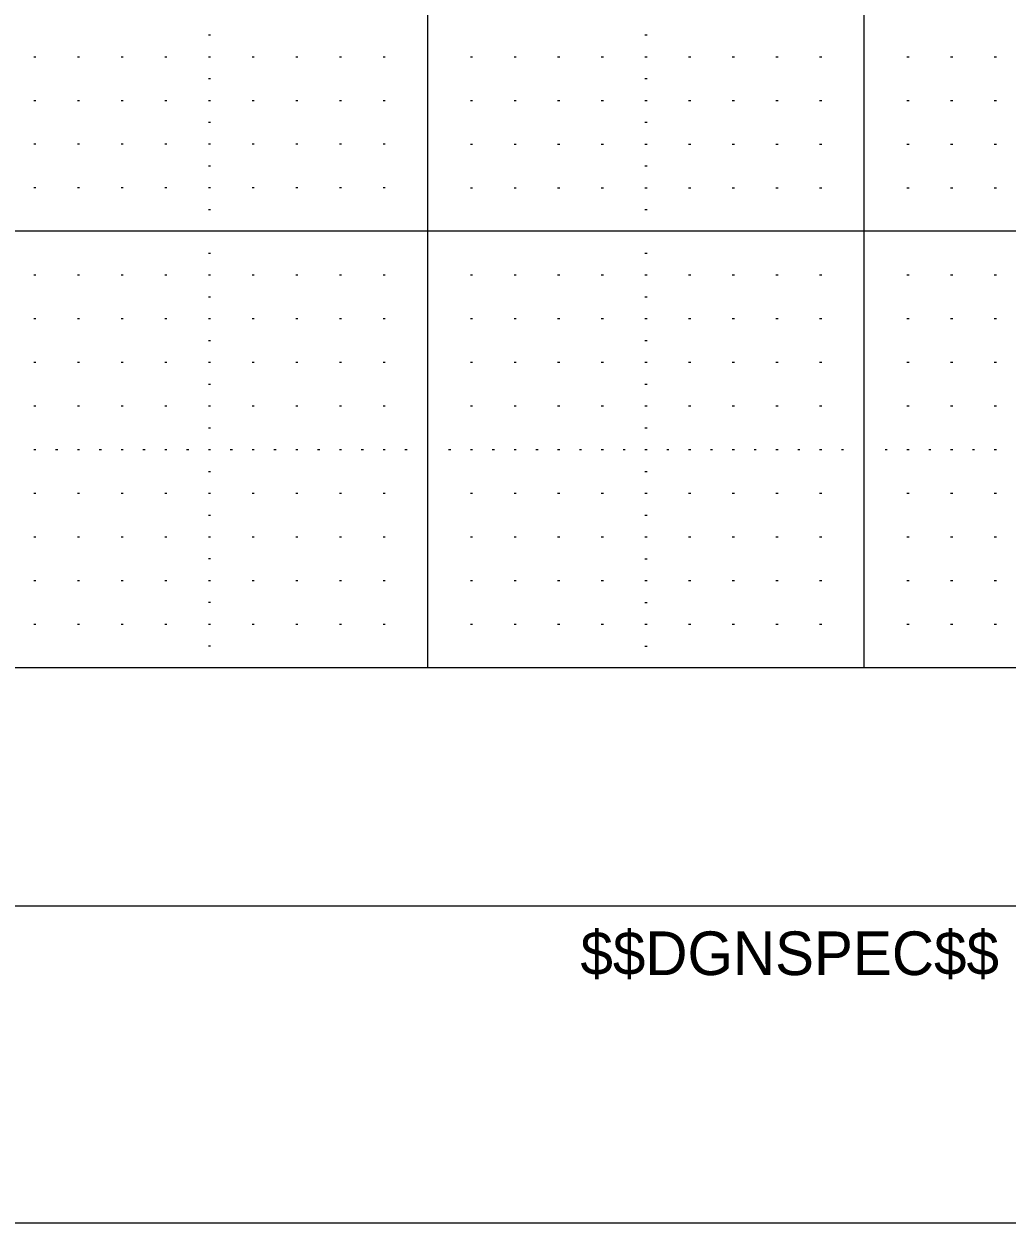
# Model space of a CAD drawing. Extents: x 0 to 34, y 0 to 22.
# Drawn here: x 25.481 to 27.733, y 0 to 2.747 of the extents above; entities that cross this region are included whole.
import ezdxf

# ---------------------------------------------------------------- set-up
doc = ezdxf.new("R2010")
doc.units = 0
for name, color, linetype in [('Level 1', 7, 'Continuous'), ('Level 4', 7, 'Continuous'), ('Level 48', 7, 'Continuous'), ('Level 5', 7, 'Continuous'), ('Level 63', 7, 'Continuous')]:
    doc.layers.add(name, color=color, linetype=linetype)

msp = doc.modelspace()

# ---------------------------------------------------------------- linework, layer by layer
at = {"layer": 'Level 1'}
msp.add_line((33.215, 0.726), (1.597, 0.726), dxfattribs=at)
at = {"layer": 'Level 4'}
for p, q in [((26.406, 1.272), (26.406, 21.272)), ((27.406, 1.272), (27.406, 20.272)), ((33.215, 2.272), (1.597, 2.272)), ((33.215, 1.272), (1.597, 1.272))]:
    msp.add_line(p, q, dxfattribs=at)
at = {"layer": 'Level 5'}
for p, q in [((25.9035, 2.722), (25.9085, 2.722)), ((26.9035, 2.7219), (26.9085, 2.7219)), ((25.5035, 2.672), (25.5085, 2.672)), ((25.6035, 2.672), (25.6085, 2.672)), ((25.7035, 2.672), (25.7085, 2.672)), ((25.8035, 2.672), (25.8085, 2.672)), ((25.9035, 2.672), (25.9085, 2.672)), ((26.0035, 2.672), (26.0085, 2.672)), ((26.1035, 2.672), (26.1085, 2.672)), ((26.2035, 2.672), (26.2085, 2.672)), ((26.3035, 2.672), (26.3085, 2.672)), ((26.5035, 2.6719), (26.5085, 2.6719)), ((26.6035, 2.6719), (26.6085, 2.6719)), ((26.7035, 2.6719), (26.7085, 2.6719)), ((26.8035, 2.6719), (26.8085, 2.6719)), ((26.9035, 2.6719), (26.9085, 2.6719)), ((27.0035, 2.6719), (27.0085, 2.6719)), ((27.1035, 2.6719), (27.1085, 2.6719)), ((27.2035, 2.6719), (27.2085, 2.6719)), ((27.3035, 2.6719), (27.3085, 2.6719)), ((27.5035, 2.6719), (27.5085, 2.6719)), ((27.6035, 2.6719), (27.6085, 2.6719)), ((27.7035, 2.6719), (27.7085, 2.6719)), ((25.9035, 2.622), (25.9085, 2.622)), ((26.9035, 2.6219), (26.9085, 2.6219)), ((25.5035, 2.572), (25.5085, 2.572)), ((25.6035, 2.572), (25.6085, 2.572)), ((25.7035, 2.572), (25.7085, 2.572)), ((25.8035, 2.572), (25.8085, 2.572)), ((25.9035, 2.572), (25.9085, 2.572)), ((26.0035, 2.572), (26.0085, 2.572)), ((26.1035, 2.572), (26.1085, 2.572)), ((26.2035, 2.572), (26.2085, 2.572)), ((26.3035, 2.572), (26.3085, 2.572)), ((26.5035, 2.5719), (26.5085, 2.5719)), ((26.6035, 2.5719), (26.6085, 2.5719)), ((26.7035, 2.5719), (26.7085, 2.5719)), ((26.8035, 2.5719), (26.8085, 2.5719)), ((26.9035, 2.5719), (26.9085, 2.5719)), ((27.0035, 2.5719), (27.0085, 2.5719)), ((27.1035, 2.5719), (27.1085, 2.5719)), ((27.2035, 2.5719), (27.2085, 2.5719)), ((27.3035, 2.5719), (27.3085, 2.5719)), ((27.5035, 2.5719), (27.5085, 2.5719)), ((27.6035, 2.5719), (27.6085, 2.5719)), ((27.7035, 2.5719), (27.7085, 2.5719)), ((25.9035, 2.522), (25.9085, 2.522)), ((26.9035, 2.5219), (26.9085, 2.5219)), ((25.5035, 2.472), (25.5085, 2.472)), ((25.6035, 2.472), (25.6085, 2.472)), ((25.7035, 2.472), (25.7085, 2.472)), ((25.8035, 2.472), (25.8085, 2.472)), ((25.9035, 2.472), (25.9085, 2.472)), ((26.0035, 2.472), (26.0085, 2.472)), ((26.1035, 2.472), (26.1085, 2.472)), ((26.2035, 2.472), (26.2085, 2.472)), ((26.3035, 2.472), (26.3085, 2.472)), ((26.5035, 2.4719), (26.5085, 2.4719)), ((26.6035, 2.4719), (26.6085, 2.4719)), ((26.7035, 2.4719), (26.7085, 2.4719)), ((26.8035, 2.4719), (26.8085, 2.4719)), ((26.9035, 2.4719), (26.9085, 2.4719)), ((27.0035, 2.4719), (27.0085, 2.4719)), ((27.1035, 2.4719), (27.1085, 2.4719)), ((27.2035, 2.4719), (27.2085, 2.4719)), ((27.3035, 2.4719), (27.3085, 2.4719)), ((27.5035, 2.4719), (27.5085, 2.4719)), ((27.6035, 2.4719), (27.6085, 2.4719)), ((27.7035, 2.4719), (27.7085, 2.4719)), ((25.9035, 2.422), (25.9085, 2.422)), ((26.9035, 2.4219), (26.9085, 2.4219)), ((25.5035, 2.372), (25.5085, 2.372)), ((25.6035, 2.372), (25.6085, 2.372)), ((25.7035, 2.372), (25.7085, 2.372)), ((25.8035, 2.372), (25.8085, 2.372)), ((25.9035, 2.372), (25.9085, 2.372)), ((26.0035, 2.372), (26.0085, 2.372)), ((26.1035, 2.372), (26.1085, 2.372)), ((26.2035, 2.372), (26.2085, 2.372)), ((26.3035, 2.372), (26.3085, 2.372)), ((26.5035, 2.3719), (26.5085, 2.3719)), ((26.6035, 2.3719), (26.6085, 2.3719)), ((26.7035, 2.3719), (26.7085, 2.3719)), ((26.8035, 2.3719), (26.8085, 2.3719)), ((26.9035, 2.3719), (26.9085, 2.3719)), ((27.0035, 2.3719), (27.0085, 2.3719)), ((27.1035, 2.3719), (27.1085, 2.3719)), ((27.2035, 2.3719), (27.2085, 2.3719)), ((27.3035, 2.3719), (27.3085, 2.3719)), ((27.5035, 2.3719), (27.5085, 2.3719)), ((27.6035, 2.3719), (27.6085, 2.3719)), ((27.7035, 2.3719), (27.7085, 2.3719)), ((25.9035, 2.322), (25.9085, 2.322)), ((26.9035, 2.3219), (26.9085, 2.3219)), ((25.9035, 2.222), (25.9085, 2.222)), ((26.9035, 2.2219), (26.9085, 2.2219)), ((25.5035, 2.172), (25.5085, 2.172)), ((25.6035, 2.172), (25.6085, 2.172)), ((25.7035, 2.172), (25.7085, 2.172)), ((25.8035, 2.172), (25.8085, 2.172)), ((25.9035, 2.172), (25.9085, 2.172)), ((26.0035, 2.172), (26.0085, 2.172)), ((26.1035, 2.172), (26.1085, 2.172)), ((26.2035, 2.172), (26.2085, 2.172)), ((26.3035, 2.172), (26.3085, 2.172)), ((26.5035, 2.1719), (26.5085, 2.1719)), ((26.6035, 2.1719), (26.6085, 2.1719)), ((26.7035, 2.1719), (26.7085, 2.1719)), ((26.8035, 2.1719), (26.8085, 2.1719)), ((26.9035, 2.1719), (26.9085, 2.1719)), ((27.0035, 2.1719), (27.0085, 2.1719)), ((27.1035, 2.1719), (27.1085, 2.1719)), ((27.2035, 2.1719), (27.2085, 2.1719)), ((27.3035, 2.1719), (27.3085, 2.1719)), ((27.5035, 2.1719), (27.5085, 2.1719)), ((27.6035, 2.1719), (27.6085, 2.1719)), ((27.7035, 2.1719), (27.7085, 2.1719)), ((25.9035, 2.122), (25.9085, 2.122)), ((26.9035, 2.1219), (26.9085, 2.1219)), ((25.5035, 2.072), (25.5085, 2.072)), ((25.6035, 2.072), (25.6085, 2.072)), ((25.7035, 2.072), (25.7085, 2.072)), ((25.8035, 2.072), (25.8085, 2.072)), ((25.9035, 2.072), (25.9085, 2.072)), ((26.0035, 2.072), (26.0085, 2.072)), ((26.1035, 2.072), (26.1085, 2.072)), ((26.2035, 2.072), (26.2085, 2.072)), ((26.3035, 2.072), (26.3085, 2.072)), ((26.5035, 2.0719), (26.5085, 2.0719)), ((26.6035, 2.0719), (26.6085, 2.0719)), ((26.7035, 2.0719), (26.7085, 2.0719)), ((26.8035, 2.0719), (26.8085, 2.0719)), ((26.9035, 2.0719), (26.9085, 2.0719)), ((27.0035, 2.0719), (27.0085, 2.0719)), ((27.1035, 2.0719), (27.1085, 2.0719)), ((27.2035, 2.0719), (27.2085, 2.0719)), ((27.3035, 2.0719), (27.3085, 2.0719)), ((27.5035, 2.0719), (27.5085, 2.0719)), ((27.6035, 2.0719), (27.6085, 2.0719)), ((27.7035, 2.0719), (27.7085, 2.0719)), ((25.9035, 2.022), (25.9085, 2.022)), ((26.9035, 2.0219), (26.9085, 2.0219)), ((25.5035, 1.972), (25.5085, 1.972)), ((25.6035, 1.972), (25.6085, 1.972)), ((25.7035, 1.972), (25.7085, 1.972)), ((25.8035, 1.972), (25.8085, 1.972)), ((25.9035, 1.972), (25.9085, 1.972)), ((26.0035, 1.972), (26.0085, 1.972)), ((26.1035, 1.972), (26.1085, 1.972)), ((26.2035, 1.972), (26.2085, 1.972)), ((26.3035, 1.972), (26.3085, 1.972)), ((26.5035, 1.9719), (26.5085, 1.9719)), ((26.6035, 1.9719), (26.6085, 1.9719)), ((26.7035, 1.9719), (26.7085, 1.9719)), ((26.8035, 1.9719), (26.8085, 1.9719)), ((26.9035, 1.9719), (26.9085, 1.9719)), ((27.0035, 1.9719), (27.0085, 1.9719)), ((27.1035, 1.9719), (27.1085, 1.9719)), ((27.2035, 1.9719), (27.2085, 1.9719)), ((27.3035, 1.9719), (27.3085, 1.9719)), ((27.5035, 1.9719), (27.5085, 1.9719)), ((27.6035, 1.9719), (27.6085, 1.9719)), ((27.7035, 1.9719), (27.7085, 1.9719)), ((25.9035, 1.922), (25.9085, 1.922)), ((26.9035, 1.9219), (26.9085, 1.9219)), ((25.5035, 1.872), (25.5085, 1.872)), ((25.6035, 1.872), (25.6085, 1.872)), ((25.7035, 1.872), (25.7085, 1.872)), ((25.8035, 1.872), (25.8085, 1.872)), ((25.9035, 1.872), (25.9085, 1.872)), ((26.0035, 1.872), (26.0085, 1.872)), ((26.1035, 1.872), (26.1085, 1.872)), ((26.2035, 1.872), (26.2085, 1.872)), ((26.3035, 1.872), (26.3085, 1.872)), ((26.5035, 1.8719), (26.5085, 1.8719)), ((26.6035, 1.8719), (26.6085, 1.8719)), ((26.7035, 1.8719), (26.7085, 1.8719)), ((26.8035, 1.8719), (26.8085, 1.8719)), ((26.9035, 1.8719), (26.9085, 1.8719)), ((27.0035, 1.8719), (27.0085, 1.8719)), ((27.1035, 1.8719), (27.1085, 1.8719)), ((27.2035, 1.8719), (27.2085, 1.8719)), ((27.3035, 1.8719), (27.3085, 1.8719)), ((27.5035, 1.8719), (27.5085, 1.8719)), ((27.6035, 1.8719), (27.6085, 1.8719)), ((27.7035, 1.8719), (27.7085, 1.8719)), ((25.9035, 1.822), (25.9085, 1.822)), ((26.9035, 1.8219), (26.9085, 1.8219)), ((25.5035, 1.772), (25.5085, 1.772)), ((25.5535, 1.772), (25.5585, 1.772)), ((25.6035, 1.772), (25.6085, 1.772)), ((25.6535, 1.772), (25.6585, 1.772)), ((25.7035, 1.772), (25.7085, 1.772)), ((25.7535, 1.772), (25.7585, 1.772)), ((25.8035, 1.772), (25.8085, 1.772)), ((25.8535, 1.772), (25.8585, 1.772)), ((25.9035, 1.772), (25.9085, 1.772)), ((25.9535, 1.772), (25.9585, 1.772)), ((26.0035, 1.772), (26.0085, 1.772)), ((26.0535, 1.772), (26.0585, 1.772)), ((26.1035, 1.772), (26.1085, 1.772)), ((26.1535, 1.772), (26.1585, 1.772)), ((26.2035, 1.772), (26.2085, 1.772)), ((26.2535, 1.772), (26.2585, 1.772)), ((26.3035, 1.772), (26.3085, 1.772)), ((26.3535, 1.772), (26.3585, 1.772)), ((26.4535, 1.7719), (26.4585, 1.7719)), ((26.5035, 1.7719), (26.5085, 1.7719)), ((26.5535, 1.7719), (26.5585, 1.7719)), ((26.6035, 1.7719), (26.6085, 1.7719)), ((26.6535, 1.7719), (26.6585, 1.7719)), ((26.7035, 1.7719), (26.7085, 1.7719)), ((26.7535, 1.7719), (26.7585, 1.7719)), ((26.8035, 1.7719), (26.8085, 1.7719)), ((26.8535, 1.7719), (26.8585, 1.7719)), ((26.9035, 1.7719), (26.9085, 1.7719)), ((26.9535, 1.7719), (26.9585, 1.7719)), ((27.0035, 1.7719), (27.0085, 1.7719)), ((27.0535, 1.7719), (27.0585, 1.7719)), ((27.1035, 1.7719), (27.1085, 1.7719)), ((27.1535, 1.7719), (27.1585, 1.7719)), ((27.2035, 1.7719), (27.2085, 1.7719)), ((27.2535, 1.7719), (27.2585, 1.7719)), ((27.3035, 1.7719), (27.3085, 1.7719)), ((27.3535, 1.7719), (27.3585, 1.7719)), ((27.4535, 1.7719), (27.4585, 1.7719)), ((27.5035, 1.7719), (27.5085, 1.7719)), ((27.5535, 1.7719), (27.5585, 1.7719)), ((27.6035, 1.7719), (27.6085, 1.7719)), ((27.6535, 1.7719), (27.6585, 1.7719)), ((27.7035, 1.7719), (27.7085, 1.7719)), ((25.9035, 1.722), (25.9085, 1.722)), ((26.9035, 1.7219), (26.9085, 1.7219)), ((25.5035, 1.672), (25.5085, 1.672)), ((25.6035, 1.672), (25.6085, 1.672)), ((25.7035, 1.672), (25.7085, 1.672)), ((25.8035, 1.672), (25.8085, 1.672)), ((25.9035, 1.672), (25.9085, 1.672)), ((26.0035, 1.672), (26.0085, 1.672)), ((26.1035, 1.672), (26.1085, 1.672)), ((26.2035, 1.672), (26.2085, 1.672)), ((26.3035, 1.672), (26.3085, 1.672)), ((26.5035, 1.6719), (26.5085, 1.6719)), ((26.6035, 1.6719), (26.6085, 1.6719)), ((26.7035, 1.6719), (26.7085, 1.6719)), ((26.8035, 1.6719), (26.8085, 1.6719)), ((26.9035, 1.6719), (26.9085, 1.6719)), ((27.0035, 1.6719), (27.0085, 1.6719)), ((27.1035, 1.6719), (27.1085, 1.6719)), ((27.2035, 1.6719), (27.2085, 1.6719)), ((27.3035, 1.6719), (27.3085, 1.6719)), ((27.5035, 1.6719), (27.5085, 1.6719)), ((27.6035, 1.6719), (27.6085, 1.6719)), ((27.7035, 1.6719), (27.7085, 1.6719)), ((25.9035, 1.622), (25.9085, 1.622)), ((26.9035, 1.6219), (26.9085, 1.6219)), ((25.5035, 1.572), (25.5085, 1.572)), ((25.6035, 1.572), (25.6085, 1.572)), ((25.7035, 1.572), (25.7085, 1.572)), ((25.8035, 1.572), (25.8085, 1.572)), ((25.9035, 1.572), (25.9085, 1.572)), ((26.0035, 1.572), (26.0085, 1.572)), ((26.1035, 1.572), (26.1085, 1.572)), ((26.2035, 1.572), (26.2085, 1.572)), ((26.3035, 1.572), (26.3085, 1.572)), ((26.5035, 1.5719), (26.5085, 1.5719)), ((26.6035, 1.5719), (26.6085, 1.5719)), ((26.7035, 1.5719), (26.7085, 1.5719)), ((26.8035, 1.5719), (26.8085, 1.5719)), ((26.9035, 1.5719), (26.9085, 1.5719)), ((27.0035, 1.5719), (27.0085, 1.5719)), ((27.1035, 1.5719), (27.1085, 1.5719)), ((27.2035, 1.5719), (27.2085, 1.5719)), ((27.3035, 1.5719), (27.3085, 1.5719)), ((27.5035, 1.5719), (27.5085, 1.5719)), ((27.6035, 1.5719), (27.6085, 1.5719)), ((27.7035, 1.5719), (27.7085, 1.5719)), ((25.9035, 1.522), (25.9085, 1.522)), ((26.9035, 1.5219), (26.9085, 1.5219)), ((25.5035, 1.472), (25.5085, 1.472)), ((25.6035, 1.472), (25.6085, 1.472)), ((25.7035, 1.472), (25.7085, 1.472)), ((25.8035, 1.472), (25.8085, 1.472)), ((25.9035, 1.472), (25.9085, 1.472)), ((26.0035, 1.472), (26.0085, 1.472)), ((26.1035, 1.472), (26.1085, 1.472)), ((26.2035, 1.472), (26.2085, 1.472)), ((26.3035, 1.472), (26.3085, 1.472)), ((26.5035, 1.4719), (26.5085, 1.4719)), ((26.6035, 1.4719), (26.6085, 1.4719)), ((26.7035, 1.4719), (26.7085, 1.4719)), ((26.8035, 1.4719), (26.8085, 1.4719)), ((26.9035, 1.4719), (26.9085, 1.4719)), ((27.0035, 1.4719), (27.0085, 1.4719)), ((27.1035, 1.4719), (27.1085, 1.4719)), ((27.2035, 1.4719), (27.2085, 1.4719)), ((27.3035, 1.4719), (27.3085, 1.4719)), ((27.5035, 1.4719), (27.5085, 1.4719)), ((27.6035, 1.4719), (27.6085, 1.4719)), ((27.7035, 1.4719), (27.7085, 1.4719)), ((25.9035, 1.422), (25.9085, 1.422)), ((26.9035, 1.4219), (26.9085, 1.4219)), ((25.5035, 1.372), (25.5085, 1.372)), ((25.6035, 1.372), (25.6085, 1.372)), ((25.7035, 1.372), (25.7085, 1.372)), ((25.8035, 1.372), (25.8085, 1.372)), ((25.9035, 1.372), (25.9085, 1.372)), ((26.0035, 1.372), (26.0085, 1.372)), ((26.1035, 1.372), (26.1085, 1.372)), ((26.2035, 1.372), (26.2085, 1.372)), ((26.3035, 1.372), (26.3085, 1.372)), ((26.5035, 1.3719), (26.5085, 1.3719)), ((26.6035, 1.3719), (26.6085, 1.3719)), ((26.7035, 1.3719), (26.7085, 1.3719)), ((26.8035, 1.3719), (26.8085, 1.3719)), ((26.9035, 1.3719), (26.9085, 1.3719)), ((27.0035, 1.3719), (27.0085, 1.3719)), ((27.1035, 1.3719), (27.1085, 1.3719)), ((27.2035, 1.3719), (27.2085, 1.3719)), ((27.3035, 1.3719), (27.3085, 1.3719)), ((27.5035, 1.3719), (27.5085, 1.3719)), ((27.6035, 1.3719), (27.6085, 1.3719)), ((27.7035, 1.3719), (27.7085, 1.3719)), ((25.9035, 1.322), (25.9085, 1.322)), ((26.9035, 1.3219), (26.9085, 1.3219))]:
    msp.add_line(p, q, dxfattribs=at)
at = {"layer": 'Level 63'}
msp.add_lwpolyline([(0, 22), (34, 22), (34, 0), (0, 0)], close=True, dxfattribs=at)

# ---------------------------------------------------------------- texts
at = {"layer": 'Level 48'}
msp.add_text('$$DGNSPEC$$', height=0.100002, dxfattribs=at).set_placement((26.7556, 0.568))

doc.saveas('drawing.dxf')
